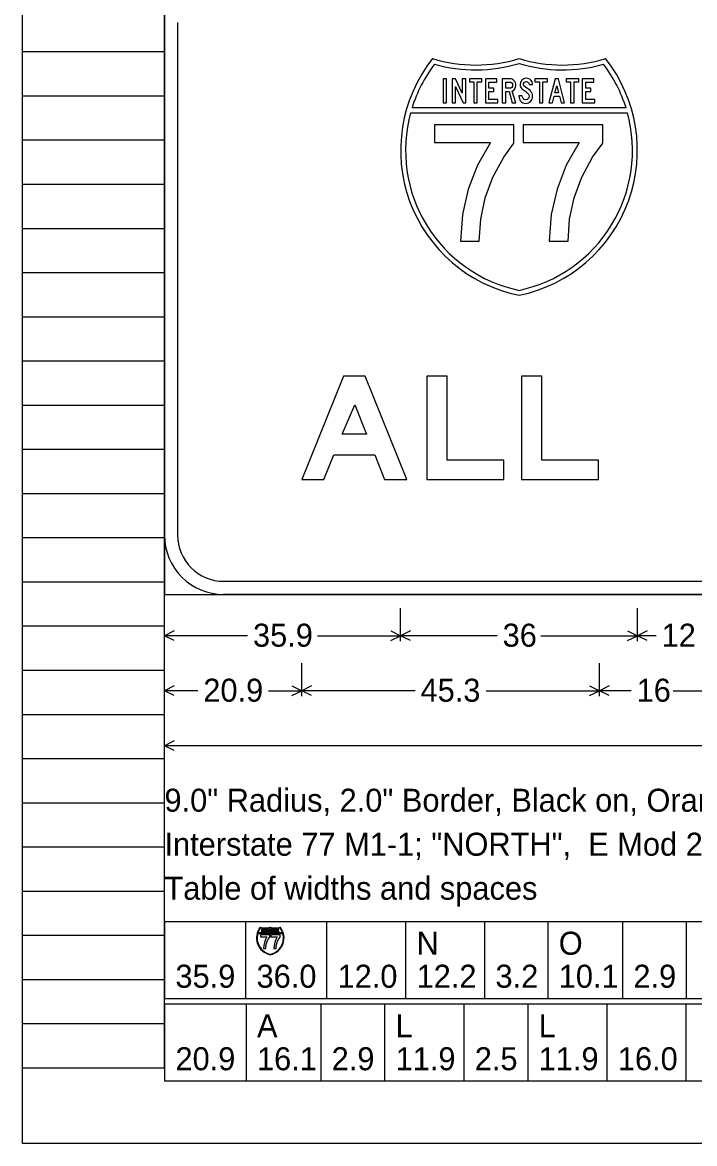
# Model space of a CAD drawing. Extents: x 1820207 to 1820557, y 740216 to 740315.
# Drawn here: x 1820476.45 to 1820480.71, y 740293.6 to 740300.71 of the extents above; entities that cross this region are included whole.
import ezdxf

# ---------------------------------------------------------------- set-up
doc = ezdxf.new("R2010")
doc.units = 0
for name, color, linetype in [('SC_Scratch1', 7, 'Continuous'), ('SC_Scratch2', 7, 'Continuous'), ('SC_Scratch3', 7, 'Continuous')]:
    doc.layers.add(name, color=color, linetype=linetype)

msp = doc.modelspace()

# ---------------------------------------------------------------- linework, layer by layer
at = {"layer": 'SC_Scratch1'}
for p, q in [((1820476.451, 740294.0812), (1820476.451, 740314.2412)), ((1820477.351, 740294.0812), (1820477.351, 740314.2412)), ((1820476.451, 740300.5212), (1820477.351, 740300.5212)), ((1820476.451, 740300.2412), (1820477.351, 740300.2412)), ((1820476.451, 740299.9612), (1820477.351, 740299.9612)), ((1820476.451, 740299.6812), (1820477.351, 740299.6812)), ((1820476.451, 740299.4012), (1820477.351, 740299.4012)), ((1820476.451, 740299.1212), (1820477.351, 740299.1212)), ((1820476.451, 740298.8412), (1820477.351, 740298.8412)), ((1820476.451, 740298.5612), (1820477.351, 740298.5612)), ((1820476.451, 740298.2812), (1820477.351, 740298.2812)), ((1820476.451, 740298.0012), (1820477.351, 740298.0012)), ((1820476.451, 740297.7212), (1820477.351, 740297.7212)), ((1820476.451, 740297.4412), (1820477.351, 740297.4412)), ((1820476.451, 740297.1612), (1820477.351, 740297.1612)), ((1820476.451, 740296.8812), (1820477.351, 740296.8812)), ((1820476.451, 740296.6012), (1820477.351, 740296.6012)), ((1820476.451, 740296.3212), (1820477.351, 740296.3212)), ((1820476.451, 740296.0412), (1820477.351, 740296.0412)), ((1820476.451, 740295.7612), (1820477.351, 740295.7612)), ((1820476.451, 740295.4812), (1820477.351, 740295.4812)), ((1820476.451, 740295.2012), (1820477.351, 740295.2012)), ((1820476.451, 740294.9212), (1820477.351, 740294.9212)), ((1820476.451, 740294.6412), (1820477.351, 740294.6412)), ((1820476.451, 740294.3612), (1820477.351, 740294.3612)), ((1820476.451, 740294.0812), (1820477.351, 740294.0812))]:
    msp.add_line(p, q, dxfattribs=at)
at = {"layer": 'SC_Scratch2'}
msp.add_lwpolyline([(1820476.451, 740314.6012), (1820506.951, 740314.6012), (1820506.951, 740293.6012), (1820476.451, 740293.6012)], close=True, dxfattribs=at)
at = {"layer": 'SC_Scratch3'}
for p, q in [((1820480.2757, 740300.1645), (1820478.9199, 740300.1645)), ((1820478.9108, 740300.1333), (1820480.2849, 740300.1333)), ((1820477.351, 740296.0877), (1820477.351, 740297.0463)), ((1820477.351, 740296.7849), (1820477.351, 740296.994)), ((1820478.8478, 740296.7849), (1820478.8478, 740296.994)), ((1820480.3478, 740296.7849), (1820480.3478, 740296.994)), ((1820477.4133, 740296.8509), (1820477.351, 740296.8197)), ((1820477.8773, 740296.8197), (1820477.351, 740296.8197)), ((1820477.4133, 740296.7885), (1820477.351, 740296.8197)), ((1820478.3215, 740296.8197), (1820478.8478, 740296.8197)), ((1820478.7855, 740296.8509), (1820478.8478, 740296.8197)), ((1820478.7855, 740296.7885), (1820478.8478, 740296.8197)), ((1820478.9102, 740296.8509), (1820478.8478, 740296.8197)), ((1820479.459, 740296.8197), (1820478.8478, 740296.8197)), ((1820478.9102, 740296.7885), (1820478.8478, 740296.8197)), ((1820479.7367, 740296.8197), (1820480.3478, 740296.8197)), ((1820480.2855, 740296.8509), (1820480.3478, 740296.8197)), ((1820480.2855, 740296.7885), (1820480.3478, 740296.8197)), ((1820480.4102, 740296.8509), (1820480.3478, 740296.8197)), ((1820480.4666, 740296.8197), (1820480.3478, 740296.8197)), ((1820480.4102, 740296.7885), (1820480.3478, 740296.8197)), ((1820477.351, 740296.4363), (1820477.351, 740296.6454)), ((1820478.221, 740296.4363), (1820478.221, 740296.6454)), ((1820480.1076, 740296.4363), (1820480.1076, 740296.6454)), ((1820477.4133, 740296.5023), (1820477.351, 740296.4711)), ((1820477.5624, 740296.4711), (1820477.351, 740296.4711)), ((1820477.4133, 740296.44), (1820477.351, 740296.4711)), ((1820478.0095, 740296.4711), (1820478.221, 740296.4711)), ((1820478.1586, 740296.5023), (1820478.221, 740296.4711)), ((1820478.1586, 740296.44), (1820478.221, 740296.4711)), ((1820478.2833, 740296.5023), (1820478.221, 740296.4711)), ((1820478.9389, 740296.4711), (1820478.221, 740296.4711)), ((1820478.2833, 740296.44), (1820478.221, 740296.4711)), ((1820479.3897, 740296.4711), (1820480.1076, 740296.4711)), ((1820480.0452, 740296.5023), (1820480.1076, 740296.4711)), ((1820480.0452, 740296.44), (1820480.1076, 740296.4711)), ((1820480.17, 740296.5023), (1820480.1076, 740296.4711)), ((1820480.3083, 740296.4711), (1820480.1076, 740296.4711)), ((1820480.17, 740296.44), (1820480.1076, 740296.4711)), ((1820480.5736, 740296.4711), (1820480.7743, 740296.4711)), ((1820477.4133, 740296.1537), (1820477.351, 740296.1226)), ((1820480.9135, 740296.1226), (1820477.351, 740296.1226)), ((1820477.4133, 740296.0914), (1820477.351, 740296.1226)), ((1820477.351, 740295.0071), (1820477.351, 740294.519)), ((1820483.1737, 740295.0071), (1820477.351, 740295.0071)), ((1820477.8649, 740295.0071), (1820477.8649, 740294.519)), ((1820478.3781, 740295.0071), (1820478.3781, 740294.519)), ((1820478.8789, 740295.0071), (1820478.8789, 740294.519)), ((1820479.379, 740295.0071), (1820479.379, 740294.519)), ((1820479.7797, 740295.0071), (1820479.7797, 740294.519)), ((1820480.2528, 740295.0071), (1820480.2528, 740294.519)), ((1820480.658, 740295.0071), (1820480.658, 740294.519)), ((1820477.9419, 740294.9323), (1820478.1016, 740294.9323)), ((1820478.1005, 740294.9359), (1820477.943, 740294.9359)), ((1820483.1737, 740294.519), (1820477.351, 740294.519)), ((1820477.351, 740294.4842), (1820477.351, 740293.9962)), ((1820485.2572, 740294.4842), (1820477.351, 740294.4842)), ((1820477.8678, 740294.4842), (1820477.8678, 740293.9962)), ((1820478.3409, 740294.4842), (1820478.3409, 740293.9962)), ((1820478.746, 740294.4842), (1820478.746, 740293.9962)), ((1820479.2476, 740294.4842), (1820479.2476, 740293.9962)), ((1820479.6527, 740294.4842), (1820479.6527, 740293.9962)), ((1820480.1543, 740294.4842), (1820480.1543, 740293.9962)), ((1820480.6551, 740294.4842), (1820480.6551, 740293.9962)), ((1820485.2572, 740293.9962), (1820477.351, 740293.9962))]:
    msp.add_line(p, q, dxfattribs=at)
for points in [[(1820477.351, 740297.0812), (1820484.851, 740297.0812), (1820484.851, 740301.0812), (1820477.351, 740301.0812), (1820477.351, 740297.0812), (1820477.351, 740297.0812), (1820477.351, 740297.0812)], [(1820477.351, 740297.4562), (1820477.351, 740300.7062)], [(1820477.4343, 740300.7062), (1820477.4343, 740297.4562)], [(1820477.4343, 740300.7062), (1820477.4343, 740300.7062), (1820477.4343, 740300.7062)], [(1820478.9108, 740300.1333), (1820478.9108, 740300.1333), (1820478.9108, 740300.1333)], [(1820477.726, 740297.1645), (1820484.476, 740297.1645)], [(1820477.726, 740297.1645), (1820477.726, 740297.1645), (1820477.726, 740297.1645)], [(1820484.476, 740297.0812), (1820477.726, 740297.0812)]]:
    msp.add_lwpolyline(points, dxfattribs=at)
for points in [[(1820479.1174, 740300.1958), (1820479.139, 740300.1958), (1820479.139, 740300.349), (1820479.1174, 740300.349)], [(1820479.1736, 740300.1958), (1820479.1946, 740300.1958), (1820479.1946, 740300.2993), (1820479.243, 740300.1958), (1820479.2601, 740300.1958), (1820479.2601, 740300.349), (1820479.2367, 740300.349), (1820479.2367, 740300.2576), (1820479.1946, 740300.349), (1820479.1736, 740300.349)], [(1820479.311, 740300.1958), (1820479.3332, 740300.1958), (1820479.3332, 740300.3297), (1820479.3618, 740300.3297), (1820479.3618, 740300.349), (1820479.283, 740300.349), (1820479.283, 740300.3297), (1820479.311, 740300.3297)], [(1820479.4634, 740300.2168), (1820479.4069, 740300.2168), (1820479.4069, 740300.2679), (1820479.4389, 740300.2679), (1820479.4389, 740300.2889), (1820479.4069, 740300.2889), (1820479.4069, 740300.328), (1820479.4575, 740300.328), (1820479.4575, 740300.349), (1820479.3845, 740300.349), (1820479.3845, 740300.1958), (1820479.4634, 740300.1958)], [(1820479.4908, 740300.1958), (1820479.5148, 740300.1958), (1820479.5148, 740300.2687), (1820479.5353, 740300.2687), (1820479.5553, 740300.1958), (1820479.5773, 740300.1958), (1820479.5551, 740300.2713), (1820479.5645, 740300.2766), (1820479.5718, 740300.2851), (1820479.5759, 740300.2949), (1820479.5773, 740300.3061), (1820479.5767, 740300.3153), (1820479.5747, 740300.3235), (1820479.5714, 740300.3308), (1820479.5669, 740300.337), (1820479.561, 740300.3422), (1820479.5539, 740300.346), (1820479.5458, 740300.3482), (1820479.5366, 740300.349), (1820479.4908, 740300.349)], [(1820479.5148, 740300.2889), (1820479.5148, 740300.328), (1820479.5373, 740300.328), (1820479.5452, 740300.3266), (1820479.5515, 740300.3227), (1820479.5555, 740300.3164), (1820479.5569, 740300.3083), (1820479.5557, 740300.2998), (1820479.5522, 740300.2937), (1820479.5463, 740300.2901), (1820479.5381, 740300.2889)], [(1820479.597, 740300.2418), (1820479.597, 740300.2404), (1820479.5977, 740300.2311), (1820479.5999, 740300.2224), (1820479.6037, 740300.2145), (1820479.6089, 740300.2073), (1820479.6155, 740300.2009), (1820479.623, 740300.1964), (1820479.6313, 740300.1937), (1820479.6405, 740300.1928), (1820479.6496, 740300.1936), (1820479.6579, 740300.1963), (1820479.6652, 740300.2006), (1820479.6718, 740300.2068), (1820479.6769, 740300.2139), (1820479.6806, 740300.2218), (1820479.6828, 740300.2303), (1820479.6836, 740300.2395), (1820479.6827, 740300.2484), (1820479.6801, 740300.2569), (1820479.6758, 740300.2649), (1820479.6698, 740300.2724), (1820479.6582, 740300.2824), (1820479.6405, 740300.2946), (1820479.6287, 740300.3034), (1820479.6261, 740300.3079), (1820479.6253, 740300.313), (1820479.6267, 740300.3198), (1820479.6308, 740300.3256), (1820479.6368, 740300.3295), (1820479.6438, 740300.3308), (1820479.6514, 740300.3296), (1820479.657, 740300.3259), (1820479.66, 740300.3207), (1820479.6623, 740300.313), (1820479.6836, 740300.313), (1820479.6801, 740300.3287), (1820479.672, 740300.341), (1820479.666, 740300.3458), (1820479.6593, 740300.3492), (1820479.6516, 740300.3513), (1820479.6432, 740300.352), (1820479.6354, 740300.3512), (1820479.6282, 740300.349), (1820479.6216, 740300.3453), (1820479.6156, 740300.3402), (1820479.6068, 740300.3273), (1820479.604, 740300.3124), (1820479.6047, 740300.3047), (1820479.6069, 740300.2976), (1820479.6105, 740300.2911), (1820479.6157, 740300.2852), (1820479.6406, 740300.2674), (1820479.6499, 740300.2604), (1820479.6556, 740300.2551), (1820479.6607, 740300.2475), (1820479.6624, 740300.2393), (1820479.6609, 740300.2303), (1820479.6565, 740300.2226), (1820479.6493, 740300.2169), (1820479.6405, 740300.215), (1820479.631, 740300.2171), (1820479.6237, 740300.2234), (1820479.6195, 740300.2318), (1820479.6182, 740300.2418)], [(1820479.7266, 740300.1958), (1820479.7488, 740300.1958), (1820479.7488, 740300.3297), (1820479.7774, 740300.3297), (1820479.7774, 740300.349), (1820479.6986, 740300.349), (1820479.6986, 740300.3297), (1820479.7266, 740300.3297)], [(1820479.7877, 740300.1958), (1820479.8099, 740300.1958), (1820479.8203, 740300.2379), (1820479.8533, 740300.2379), (1820479.8642, 740300.1958), (1820479.8866, 740300.1958), (1820479.8479, 740300.349), (1820479.8263, 740300.349)], [(1820479.8257, 740300.2597), (1820479.8365, 740300.3042), (1820479.8479, 740300.2597)], [(1820479.925, 740300.1958), (1820479.9473, 740300.1958), (1820479.9473, 740300.3297), (1820479.9759, 740300.3297), (1820479.9759, 740300.349), (1820479.897, 740300.349), (1820479.897, 740300.3297), (1820479.925, 740300.3297)], [(1820480.0774, 740300.2168), (1820480.021, 740300.2168), (1820480.021, 740300.2679), (1820480.053, 740300.2679), (1820480.053, 740300.2889), (1820480.021, 740300.2889), (1820480.021, 740300.328), (1820480.0716, 740300.328), (1820480.0716, 740300.349), (1820479.9986, 740300.349), (1820479.9986, 740300.1958), (1820480.0774, 740300.1958)], [(1820479.2269, 740299.3208), (1820479.3458, 740299.3208), (1820479.3552, 740299.4591), (1820479.3842, 740299.5943), (1820479.4327, 740299.7254), (1820479.5006, 740299.8532), (1820479.5659, 740299.9409), (1820479.5659, 740300.0563), (1820479.0616, 740300.0563), (1820479.0616, 740299.9461), (1820479.4169, 740299.9461), (1820479.3349, 740299.8019), (1820479.2761, 740299.6497), (1820479.24, 740299.4893)], [(1820479.7894, 740299.3208), (1820479.9083, 740299.3208), (1820479.9177, 740299.4591), (1820479.9467, 740299.5943), (1820479.9952, 740299.7254), (1820480.0631, 740299.8532), (1820480.1284, 740299.9409), (1820480.1284, 740300.0563), (1820479.6241, 740300.0563), (1820479.6241, 740299.9461), (1820479.9794, 740299.9461), (1820479.8974, 740299.8019), (1820479.8386, 740299.6497), (1820479.8025, 740299.4893)], [(1820478.221, 740297.8103), (1820478.3613, 740297.8103), (1820478.4233, 740297.9651), (1820478.6845, 740297.9651), (1820478.7463, 740297.8103), (1820478.8868, 740297.8103), (1820478.6218, 740298.4641), (1820478.4859, 740298.4641)], [(1820479.0143, 740297.8103), (1820479.5022, 740297.8103), (1820479.5022, 740297.9329), (1820479.1434, 740297.9329), (1820479.1434, 740298.4641), (1820479.0143, 740298.4641)], [(1820479.6143, 740297.8103), (1820480.1022, 740297.8103), (1820480.1022, 740297.9329), (1820479.7434, 740297.9329), (1820479.7434, 740298.4641), (1820479.6143, 740298.4641)], [(1820478.4767, 740298.0971), (1820478.5571, 740298.2817), (1820478.631, 740298.0971)], [(1820477.9787, 740294.8379), (1820477.9925, 740294.8379), (1820477.9936, 740294.8539), (1820477.9969, 740294.8696), (1820478.0026, 740294.8849), (1820478.0105, 740294.8997), (1820478.0181, 740294.9099), (1820478.0181, 740294.9233), (1820477.9595, 740294.9233), (1820477.9595, 740294.9105), (1820478.0007, 740294.9105), (1820477.9912, 740294.8938), (1820477.9844, 740294.8761), (1820477.9802, 740294.8574)], [(1820477.9659, 740294.9395), (1820477.9684, 740294.9395), (1820477.9684, 740294.9573), (1820477.9659, 740294.9573)], [(1820477.9725, 740294.9395), (1820477.9749, 740294.9395), (1820477.9749, 740294.9516), (1820477.9805, 740294.9395), (1820477.9825, 740294.9395), (1820477.9825, 740294.9573), (1820477.9798, 740294.9573), (1820477.9798, 740294.9467), (1820477.9749, 740294.9573), (1820477.9725, 740294.9573)], [(1820477.9884, 740294.9395), (1820477.991, 740294.9395), (1820477.991, 740294.9551), (1820477.9943, 740294.9551), (1820477.9943, 740294.9573), (1820477.9852, 740294.9573), (1820477.9852, 740294.9551), (1820477.9884, 740294.9551)], [(1820478.0062, 740294.942), (1820477.9996, 740294.942), (1820477.9996, 740294.9479), (1820478.0033, 740294.9479), (1820478.0033, 740294.9503), (1820477.9996, 740294.9503), (1820477.9996, 740294.9549), (1820478.0055, 740294.9549), (1820478.0055, 740294.9573), (1820477.997, 740294.9573), (1820477.997, 740294.9395), (1820478.0062, 740294.9395)], [(1820478.0093, 740294.9395), (1820478.0121, 740294.9395), (1820478.0121, 740294.948), (1820478.0145, 740294.948), (1820478.0168, 740294.9395), (1820478.0194, 740294.9395), (1820478.0168, 740294.9483), (1820478.0179, 740294.9489), (1820478.0187, 740294.9499), (1820478.0192, 740294.951), (1820478.0194, 740294.9523), (1820478.0193, 740294.9534), (1820478.0191, 740294.9544), (1820478.0187, 740294.9552), (1820478.0182, 740294.9559), (1820478.0175, 740294.9565), (1820478.0167, 740294.957), (1820478.0157, 740294.9572), (1820478.0147, 740294.9573), (1820478.0093, 740294.9573)], [(1820478.0121, 740294.9503), (1820478.0121, 740294.9549), (1820478.0147, 740294.9549), (1820478.0157, 740294.9547), (1820478.0164, 740294.9543), (1820478.0169, 740294.9535), (1820478.017, 740294.9526), (1820478.0169, 740294.9516), (1820478.0165, 740294.9509), (1820478.0158, 740294.9505), (1820478.0148, 740294.9503)], [(1820478.0217, 740294.9449), (1820478.0217, 740294.9447), (1820478.0217, 740294.9436), (1820478.022, 740294.9426), (1820478.0224, 740294.9417), (1820478.023, 740294.9409), (1820478.0238, 740294.9401), (1820478.0247, 740294.9396), (1820478.0256, 740294.9393), (1820478.0267, 740294.9392), (1820478.0278, 740294.9393), (1820478.0287, 740294.9396), (1820478.0296, 740294.9401), (1820478.0304, 740294.9408), (1820478.031, 740294.9416), (1820478.0314, 740294.9425), (1820478.0316, 740294.9435), (1820478.0317, 740294.9446), (1820478.0316, 740294.9456), (1820478.0313, 740294.9466), (1820478.0308, 740294.9476), (1820478.0301, 740294.9484), (1820478.0288, 740294.9496), (1820478.0267, 740294.951), (1820478.0253, 740294.952), (1820478.025, 740294.9526), (1820478.0249, 740294.9531), (1820478.0251, 740294.9539), (1820478.0256, 740294.9546), (1820478.0263, 740294.9551), (1820478.0271, 740294.9552), (1820478.028, 740294.9551), (1820478.0286, 740294.9546), (1820478.029, 740294.954), (1820478.0292, 740294.9532), (1820478.0317, 740294.9532), (1820478.0313, 740294.955), (1820478.0304, 740294.9564), (1820478.0297, 740294.957), (1820478.0289, 740294.9574), (1820478.028, 740294.9576), (1820478.027, 740294.9577), (1820478.0261, 740294.9576), (1820478.0253, 740294.9573), (1820478.0245, 740294.9569), (1820478.0238, 740294.9563), (1820478.0228, 740294.9548), (1820478.0225, 740294.9531), (1820478.0226, 740294.9522), (1820478.0228, 740294.9514), (1820478.0232, 740294.9506), (1820478.0238, 740294.9499), (1820478.0267, 740294.9479), (1820478.0278, 740294.947), (1820478.0285, 740294.9464), (1820478.0291, 740294.9455), (1820478.0293, 740294.9446), (1820478.0291, 740294.9435), (1820478.0286, 740294.9426), (1820478.0277, 740294.942), (1820478.0267, 740294.9418), (1820478.0256, 740294.942), (1820478.0248, 740294.9427), (1820478.0243, 740294.9437), (1820478.0241, 740294.9449)], [(1820478.044, 740294.8379), (1820478.0579, 740294.8379), (1820478.0589, 740294.8539), (1820478.0623, 740294.8696), (1820478.068, 740294.8849), (1820478.0758, 740294.8997), (1820478.0834, 740294.9099), (1820478.0834, 740294.9233), (1820478.0248, 740294.9233), (1820478.0248, 740294.9105), (1820478.0661, 740294.9105), (1820478.0566, 740294.8938), (1820478.0498, 740294.8761), (1820478.0456, 740294.8574)], [(1820478.0367, 740294.9395), (1820478.0393, 740294.9395), (1820478.0393, 740294.9551), (1820478.0426, 740294.9551), (1820478.0426, 740294.9573), (1820478.0335, 740294.9573), (1820478.0335, 740294.9551), (1820478.0367, 740294.9551)], [(1820478.0438, 740294.9395), (1820478.0464, 740294.9395), (1820478.0476, 740294.9444), (1820478.0515, 740294.9444), (1820478.0527, 740294.9395), (1820478.0553, 740294.9395), (1820478.0508, 740294.9573), (1820478.0483, 740294.9573)], [(1820478.0483, 740294.947), (1820478.0495, 740294.9521), (1820478.0508, 740294.947)], [(1820478.0598, 740294.9395), (1820478.0624, 740294.9395), (1820478.0624, 740294.9551), (1820478.0657, 740294.9551), (1820478.0657, 740294.9573), (1820478.0565, 740294.9573), (1820478.0565, 740294.9551), (1820478.0598, 740294.9551)], [(1820478.0775, 740294.942), (1820478.0709, 740294.942), (1820478.0709, 740294.9479), (1820478.0747, 740294.9479), (1820478.0747, 740294.9503), (1820478.0709, 740294.9503), (1820478.0709, 740294.9549), (1820478.0768, 740294.9549), (1820478.0768, 740294.9573), (1820478.0683, 740294.9573), (1820478.0683, 740294.9395), (1820478.0775, 740294.9395)]]:
    msp.add_lwpolyline(points, close=True, dxfattribs=at)
for centre, radius, start, end in [((1820479.7853, 740299.8955), 0.9375, 141.66897, 258.46298), ((1820479.7853, 740299.8955), 0.9375, 141.66897, 258.46298), ((1820479.7853, 740299.8955), 0.9063, 142.99594, 162.73663), ((1820479.3239, 740301.3736), 0.9375, 253.009, 286.99112), ((1820479.3239, 740301.3736), 0.9375, 253.00899, 286.99112), ((1820479.3215, 740301.3743), 0.9688, 254.4391, 286.57458), ((1820479.4103, 740299.8955), 0.9375, 281.53714, 38.33115), ((1820479.8718, 740301.3736), 0.9375, 253.009, 286.99112), ((1820479.4103, 740299.8955), 0.9375, 281.53714, 38.33114), ((1820479.8718, 740301.3736), 0.9375, 253.00899, 286.99112), ((1820479.8742, 740301.3743), 0.9688, 253.42554, 285.56102), ((1820479.4103, 740299.8955), 0.9063, 17.26328, 37.00414), ((1820479.7852, 740299.8949), 0.9063, 164.75344, 258.0705), ((1820479.4105, 740299.8949), 0.9063, 281.92961, 15.24668), ((1820477.726, 740297.4562), 0.375, 179.99985, 270.00006), ((1820477.726, 740297.4562), 0.2917, 179.99985, 270.00006), ((1820478.0435, 740294.9046), 0.1089, 141.66897, 258.46298), ((1820478.0435, 740294.9046), 0.1053, 142.99594, 162.73663), ((1820477.9899, 740295.0764), 0.1089, 253.009, 286.99112), ((1820477.9897, 740295.0765), 0.1126, 254.4391, 286.57458), ((1820478, 740294.9046), 0.1089, 281.53714, 38.33115), ((1820478.0536, 740295.0764), 0.1089, 253.009, 286.99112), ((1820478.0539, 740295.0765), 0.1126, 253.42554, 285.56102), ((1820478, 740294.9046), 0.1053, 17.26328, 37.00414), ((1820478.0435, 740294.9046), 0.1053, 164.75344, 258.0705), ((1820478, 740294.9046), 0.1053, 281.92961, 15.24668)]:
    msp.add_arc(centre, radius, start, end, dxfattribs=at)

# ---------------------------------------------------------------- texts
for s, height, p in [('35.9', 0.14583, (1820477.9121, 740296.75)), ('36', 0.14583, (1820479.4938, 740296.75)), ('12', 0.14583, (1820480.5015, 740296.75)), ('20.9', 0.14583, (1820477.5972, 740296.4014)), ('45.3', 0.14583, (1820478.9737, 740296.4014)), ('16', 0.14583, (1820480.3431, 740296.4014)), ('9.0" Radius, 2.0" Border, Black on, Orange;', 0.145833, (1820477.351, 740295.7042)), ('Interstate 77 M1-1; "NORTH",  E Mod 2K; "ALL LANES",  E Mod 2K;', 0.145833, (1820477.351, 740295.4254)), ('Table of widths and spaces', 0.145833, (1820477.351, 740295.1465)), ('N', 0.1458, (1820478.9486, 740294.7979)), ('O', 0.1458, (1820479.8495, 740294.7979)), ('35.9', 0.14583, (1820477.4207, 740294.5888)), ('36.0', 0.14583, (1820477.9346, 740294.5888)), ('12.0', 0.14583, (1820478.4478, 740294.5888)), ('12.2', 0.14583, (1820478.9486, 740294.5888)), ('3.2', 0.14583, (1820479.4487, 740294.5888)), ('10.1', 0.14583, (1820479.8495, 740294.5888)), ('2.9', 0.14583, (1820480.3225, 740294.5888)), ('A', 0.1458, (1820477.9375, 740294.275)), ('L', 0.1458, (1820478.8157, 740294.275)), ('L', 0.1458, (1820479.7225, 740294.275)), ('20.9', 0.14583, (1820477.4207, 740294.0659)), ('16.1', 0.14583, (1820477.9375, 740294.0659)), ('2.9', 0.14583, (1820478.4106, 740294.0659)), ('11.9', 0.14583, (1820478.8157, 740294.0659)), ('2.5', 0.14583, (1820479.3173, 740294.0659)), ('11.9', 0.14583, (1820479.7225, 740294.0659)), ('16.0', 0.14583, (1820480.224, 740294.0659))]:
    msp.add_text(s, height=height, dxfattribs=at).set_placement(p)

doc.saveas('drawing.dxf')
